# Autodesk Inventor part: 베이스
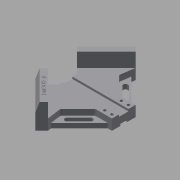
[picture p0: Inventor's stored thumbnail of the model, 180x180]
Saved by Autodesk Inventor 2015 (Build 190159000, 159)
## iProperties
Created: 2020-05
Part Number: 베이스
Material: 일반
Document SubType Name: Modeling
Designer: CAD02
Density: 1 g/cm^3
Appearance: 기본값
Author: CAD02
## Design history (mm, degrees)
sketch "스케치2"
  geometry: L1 (0, 84.853)-(-84.853, 0); L2 (-84.853, 0)-(0, -84.853); L3 (0, -84.853)-(84.853, 0); L4 (84.853, 0)-(0, 84.853); L5 (0, 84.853)-(0, -84.853); L6 (-84.853, 0)-(84.853, 0); 2 further points
  constraints: 12 end point, 3 midpoint, 2 horizontal alignment, 2 parallel, 1 perpendicular, 1 vertical alignment
  dimensions: "d2" = 120 distance of L1.start L1.end
extrude "돌출1" new body sketch "스케치2" distance "d3" = 18; taper "d4" = 0 deg
sketch "스케치3"
  geometry: L1 (0, 84.853)-(-84.853, 0) reference; L2 (-84.853, 0)-(0, -84.853) reference; L3 (-84.853, 0)-(-49.497, -35.355); L4 (-49.497, -35.355)-(-14.142, 0); L5 (-14.142, 0)-(-49.497, 35.355); L6 (-49.497, 35.355)-(-84.853, 0); 1 further point
  constraints: 8 end point, 2 parallel, 1 perpendicular, 1 point on line
  dimensions: "d5" = 50 distance between parallel lines of L1 L4; "d6" = 50 distance between parallel lines of L2 L5
extrude "돌출2" cut sketch "스케치3" stored distance "d7" = 18; taper "d8" = 0 deg
sketch "스케치4"
  geometry: L1 (84.853, 0)-(0, 84.853) reference; L2 (0, -84.853)-(84.853, 0) reference; L3 (64.853, -20)-(64.853, 20); 1 further point
  constraints: 2 end point, 2 point on line, 1 vertical
  dimensions: "d9" = 20 distance from line of L1.start L3
extrude "돌출3" cut sketch "스케치4" stored distance "d10" = 18; taper "d11" = 0 deg
sketch "스케치5"
  geometry: L1 (64.853, -20)-(64.853, 20) reference; L2 (-49.497, 35.355)-(-14.142, 0) reference; L3 (-14.142, 0)-(-49.497, -35.355) reference; L4 (-30.147, 16.005)-(-30.147, -16.005); 1 further point
  constraints: 2 end point, 2 point on line, 1 vertical
  dimensions: "d12" = 95 distance between parallel lines of L1 L4
extrude "돌출4" join sketch "스케치5" distance "d13" = 18; taper "d14" = 0 deg
sketch "스케치6"
  geometry: L1 (64.853, 20)-(0, 84.853) reference; L2 (0, 84.853)-(-49.497, 35.355) reference; L3 (-49.497, 35.355)-(-30.147, 16.005) reference; L4 (-30.147, -16.005)-(-49.497, -35.355) reference; L5 (-49.497, -35.355)-(0, -84.853) reference; L6 (0, -84.853)-(64.853, -20) reference; L7 (-49.497, -35.355)-(-38.891, -24.749); L8 (-38.891, -24.749)-(10.607, -74.246); L9 (10.607, -74.246)-(0, -84.853); L10 (0, -84.853)-(-49.497, -35.355); L11 (-38.891, 24.749)-(-49.497, 35.355); L12 (-49.497, 35.355)-(0, 84.853); L13 (0, 84.853)-(10.607, 74.246); L14 (10.607, 74.246)-(-38.891, 24.749); 1 further point
  constraints: 16 end point, 4 parallel, 3 collinear, 2 perpendicular, 2 point on line
  dimensions: "d15" = 15 distance between parallel lines of L5 L8; "d16" = 15 distance between parallel lines of L2 L14
extrude "돌출5" join sketch "스케치6" distance "d17" = 24; taper "d18" = 0 deg
sketch "스케치7"
  geometry: L1 (91.716, -24)-(76.716, -24) reference; L2 (91.716, 18)-(91.716, -24) reference; L3 (91.716, -9)-(86.716, -24); 1 further point
  constraints: 2 end point, 2 point on line
  dimensions: "d19" = 5 distance of L1.start L3.end; "d20" = 15 distance of L3.start L1.start
extrude "돌출6" cut sketch "스케치7" stored distance "d21" = 24; taper "d22" = 0 deg
sketch "스케치8"
  geometry: L1 (91.716, 0)-(91.716, 42) reference; L2 (76.716, 42)-(91.716, 42) reference; L3 (86.716, 42)-(91.716, 27); 1 further point
  constraints: 2 end point, 2 point on line
  dimensions: "d23" = 15 distance of L1.end L3.end; "d24" = 5 distance of L1.end L3.start
extrude "돌출7" cut sketch "스케치8" stored distance "d25" = 24; taper "d26" = 0 deg
sketch "스케치10"
  geometry: L1 (10.607, -74.246)-(64.853, -20) reference; L2 (10.607, -74.246)-(7.071, -49.497); L3 (7.071, -49.497)-(36.569, -20); L4 (36.569, -20)-(64.853, -20); L5 (-49.497, -35.355)-(0, -84.853) reference; 1 further point
  constraints: 6 end point, 1 horizontal, 1 parallel
  dimensions: "d27" = 20 distance between parallel lines of L1 L3; "d28" = 30 distance from line of L5 L2.end
extrude "돌출8" cut sketch "스케치10" distance "d29" = 10; taper "d30" = 0 deg
sketch "스케치11"
  geometry: L1 (64.853, -20)-(10.607, -74.246) reference; L2 (18.385, -49.497)-(38.184, -29.698); L3 (15.556, -46.669)-(35.355, -26.87); L4 (41.012, -32.527)-(21.213, -52.326); L5 (-49.497, -35.355)-(0, -84.853) reference; A1 r 4 centre (18.385, -49.497) between (15.556, -46.669) and (21.213, -52.326); A2 r 4 centre (38.184, -29.698) between (41.012, -32.527) and (35.355, -26.87); 2 further points
  constraints: 8 end point, 4 point on circle, 4 tangent, 2 centre point, 2 parallel, 1 midpoint
  dimensions: "d31" = 8 distance between parallel lines of L3 L4; "d33" = 28 distance of L4.start L4.end; "d34" = 12 distance from line of point (28.284, -39.598) L1; "d35" = 38 distance from line of L5 L4.end
extrude "돌출9" cut sketch "스케치11" stored distance "d36" = 10; taper "d37" = 0 deg
sketch "스케치12"
  geometry: L1 (64.853, -20)-(10.607, -74.246) reference; L2 (36.569, -20)-(64.853, -20) reference; L3 (10.607, -74.246)-(7.071, -49.497) reference; L4 (9.723, -68.059)-(57.782, -20); 1 further point
  constraints: 2 end point, 2 point on line, 1 parallel
  dimensions: "d38" = 5 distance between parallel lines of L1 L4
extrude "돌출10" cut sketch "스케치12" stored distance "d39" = 10; taper "d40" = 0 deg
fillet "모깎기1" dims "d41" = 5
sketch "스케치13"
  geometry: L1 (-30.147, 13.934)-(-30.147, -13.934) reference; L2 (64.853, -20)-(64.853, 20) reference; L3 (-30.147, -13.934)-(-30.147, 13.934) reference; L4 (-30.147, -8)-(-30.147, 8); L5 (-30.147, 8)-(64.853, 8); L6 (64.853, 8)-(64.853, -8); L7 (64.853, -8)-(-30.147, -8); 1 further point
  constraints: 8 end point, 2 parallel, 2 point on line, 1 collinear, 1 perpendicular
  dimensions: "d42" = 16 distance between parallel lines of L5 L7; "d43" = 8 distance from line of L5 point (0, 0)
extrude "돌출11" cut sketch "스케치13" distance "d44" = 3.5; taper "d45" = 0 deg
sketch "스케치14"
  geometry: L1 (-64.853, 20)-(-64.853, -20) reference; L2 (30.147, -13.934)-(30.147, 13.934) reference; L3 (-64.853, -6)-(-64.853, 6); L4 (-64.853, 6)-(30.147, 6); L5 (30.147, 6)-(30.147, -6); L6 (30.147, -6)-(-64.853, -6); 1 further point
  constraints: 8 end point, 2 parallel, 2 point on line, 1 collinear, 1 perpendicular
  dimensions: "d46" = 12 distance between parallel lines of L6 L4; "d47" = 6 distance from line of point (0, 0) L4
extrude "돌출12" cut sketch "스케치14" distance "d48" = 3; taper "d49" = 0 deg
sketch "스케치15"
  geometry: L1 (30.147, -6)-(-64.853, -6) reference; L2 (-64.853, -6)-(-64.853, -20) reference; 3 further points
  dimensions: "d50" = 12 distance of point (-58.853, -14) point (-46.853, -14); "d51" = 6 distance from line of L2 point (-58.853, -14); "d52" = 8 distance from line of L1 point (-58.853, -14); "d53" = 8 distance from line of L1 point (-46.853, -14)
hole "구멍1" sketch "스케치15" at (-58.853, -14), (-46.853, -14) diameter "d54" = 4.5; stored, may be unused: countersink angle "d58" = 90 deg, drill point angle "d60" = 118 deg; dims "d55" = 6, "d56" = 8, "d57" = 10, "d59" = 8
sketch "스케치16"
  geometry: L1 (10.607, -74.246)-(-38.891, -24.749) reference; L2 (-38.891, -24.749)-(-45.962, -31.82) reference; 2 further points
  constraints: 1 other
  dimensions: "d61" = 5 distance from line of L1 point (-17.678, -53.033); "d62" = 35 distance from line of L2 point (-17.678, -53.033)
feature "엠보싱1" sketch "스케치16" dims "d2" = 120, "d63" = 0.5, "d64" = 0
node "솔리드1"
mirror "대칭1"
mirror "대칭2"
mirror "대칭3"
mirror "대칭4"
